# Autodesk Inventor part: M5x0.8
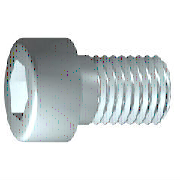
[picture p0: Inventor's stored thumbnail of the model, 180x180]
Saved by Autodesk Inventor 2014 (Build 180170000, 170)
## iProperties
IsCustomPart: 0
Manager: KYOUNG IL JANG
Company: 한국ATC센터
Created: 2009-02
Part Number: M5x0.8
Material: Steel, Mild
Description: 6각머리 태핑 나사
Document SubType Name: Modeling
Standard: KS B 1003
Standards Organization: KS
Language: ko-KR
Size Designation: M 5 x 20
Categories: <MemberInstance><Categories><Category DisplayName="조임쇠" InternalName="e4da775c-781d-43d5-af7c-5136215cf5a6" Mnemonic="FSTN"><Category DisplayName="볼트" InternalN
Density: 1 g/cm^3
Checked By: KYOUNG IL JANG
Vendor: CBT Solutions
Designer: KYOUNG IL JANG
Appearance: Metal-Steel
Author: KYOUNG IL JANG
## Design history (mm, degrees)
sketch "스케치1"
  geometry: L1 (-1.167, 0)-(20, 0); L2 (20, 0)-(20, 2.5); L3 (20, 2.5)-(2, 2.5); L4 (2, 2.5)-(1.509, 2.5); L5 (1.509, 2.5)-(0, 2.5); L6 (0, 2.5)-(0, 4.25); L7 (0, 4.25)-(-5, 4.25); L8 (-5, 4.25)-(-5, 2.309); L9 (-5, 2.309)-(-2.5, 2.309); L10 (-2.5, 2.309)-(-1.167, 0); L11 (-10, 0)-(25, 0) reference; L12 (0, -0.85)-(0, 5.1) reference; L13 (2, 2.5)-(0, 2.5)
  constraints: 22 end point, 6 parallel, 2 collinear, 2 perpendicular, 1 horizontal, 1 point on line
  dimensions: "d1" = 18 distance from line of L3.end L2 (= GEL); "d2" = 0.49086 distance of L4.end L3.end (computed from GAL); "d3" = 5 distance between parallel lines of L8 L6 (= KOH); "d4" = 2.5 distance of L8.end L9.end (= INTI); "d5" = 60 deg angle of L10 L1; "d6" = 5 diameter of L3 L1 (= GD); "d7" = 5 diameter of L5 L1 (= BDM); "d8" = 4.6188 diameter of L9 L1 (= 1.1547 x SW); "d9" = 8.5 diameter of L7 L1 (= KOD); "d26" = 20 distance between parallel lines of L12 L2 (= NLG)
revolve "본체" sketch "스케치1" stored, may be unused: angle "d10" = 90 deg
sketch "스케치2"
  geometry: L1 (0, -5.95)-(0, 5.95) reference; L2 (-5.95, 0)-(5.95, 0) reference; L3 (2.309, 0)-(1.155, -2); L4 (1.155, -2)-(-1.155, -2); L5 (-1.155, -2)-(-2.309, 0); L6 (-2.309, 0)-(-1.155, 2); L7 (-1.155, 2)-(1.155, 2); L8 (1.155, 2)-(2.309, 0); 2 further points
  constraints: 12 end point, 1 coincident, 1 horizontal alignment, 1 point on line, 12 other
extrude "슬롯" join sketch "스케치2" stored distance "d11" = 10; taper "d12" = 0 deg
workplane "Work Plane1"
fillet "Fillet2" dims "d30" = 0.1 (= R)
body "Solid1"
fillet "모깎기1" dims "d17" = 0.5 (= RR)
feature "스레드" dims "d13" = 18 (= GEL), "d14" = 0
chamfer "모따기1" distance "d15" = 0.49076 (= -0.5 x SPD + 0.5 x GD); stored, may be unused: second distance "d16" = 0.49076 (= GUL), angle "d27" = 45 deg
other parameters: "GD" = 5 (= NND) [user parameter; used in 2 equation terms], "NLG" = 20 [user parameter; used in 1 equation term], "GEL" = 18 [user parameter; used in 2 equation terms], "KOD" = 8.5 [user parameter; used in 1 equation term], "KOH" = 5 [user parameter; used in 1 equation term], "INTI" = 2.5 [user parameter; used in 1 equation term], "GAL" = 0.49076 (= 0.61345 x PTC) [user parameter; used in 1 equation term], "GUL" = 0.49076 (= 0.61345 x PTC) [user parameter; used in 1 equation term], "BDM" = 5 (= NND) [user parameter; used in 1 equation term], "SW" = 4 [user parameter; used in 2 equation terms], "RR" = 0.5 [user parameter; used in 1 equation term], "SPD" = 4.01848 (= NND - 1.2269 x PTC) [user parameter; used in 1 equation term], "d19" = 0, "d28" = 0, "d29" = 0, "R" = 0.1 [user parameter; used in 1 equation term], "PHH" = 0.2 [user parameter], "GD1" = 4.01848 (= THREADDIA - 1.2269 x PTC) [user parameter], "THREADDIA" = 5 [user parameter; used in 1 equation term], "FAWI" = 45 deg [user parameter], "TPU" = 12.5 (computed from PTC) [user parameter], "PTC" = 0.8 [user parameter; used in 5 equation terms], "NND" = 5 [user parameter; used in 3 equation terms], "TOA" = 30 deg [user parameter], "E0" = 4.62 (= 1.155 x SW) [user parameter]
